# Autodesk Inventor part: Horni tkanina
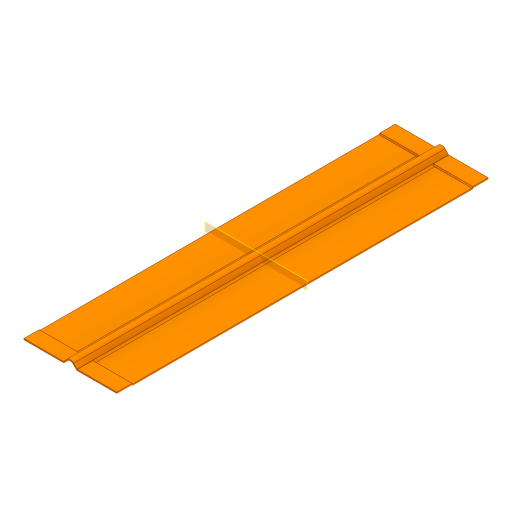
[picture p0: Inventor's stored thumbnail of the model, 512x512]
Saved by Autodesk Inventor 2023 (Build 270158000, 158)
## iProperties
Created: 2025-03
Part Number: Horni tkanina
Material: Všeobecné
Document SubType Name: Modeling
Designer: tomik
Density: 1 g/cm^3
Appearance: Výchozí(1)
Author: tomik
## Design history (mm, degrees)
sketch "Náčrt1"
  geometry: L1 (0, 0)-(0, 10.449); L2 (0, 0)-(6.785, 0); L3 (0, 0)-(0, 4); L4 (0, 0)-(4, 0); L5 (3.268, 0.732)-(0, 4); L6 (0, 0)-(-6.785, 0); L7 (0, 0)-(-4, 0); L8 (-3.268, 0.732)-(0, 4); A1 r 2.5 centre (5.036, 2.5) between (3.268, 0.732) and (5.036, 0); A2 r 2.5 centre (-5.036, 2.5) between (-5.036, 0) and (-3.268, 0.732)
  constraints: 16 end point, 5 point on line, 5 symmetric about line, 4 point on circle, 2 centre point, 2 tangent, 1 horizontal, 1 vertical, 1 other
  dimensions: "d0" = 4 distance of L1.start L3.end; "d3" = 4 distance of L1.start L4.end; "d4" = 5 diameter of A1; "d5" = 5.03553 distance from line of A1.end L1
extrude "Vysunutí1" new body sketch "Náčrt1" distance "d6" = 200; taper "d7" = 0 deg
fillet "Zaoblení1" dims "d8" = 2
feature "Zesílit1" dims "d9" = 0.6, "d10" = 2
sketch "Náčrt2"
  geometry: 1 further point
node "Pracovní rovina1"
sketch "Náčrt3"
  geometry: L1 (0, 0)-(0, 200) reference; L2 (0, 0)-(0.6, 0) reference; L3 (0, 0)-(0, 200) reference; L4 (0, 0)-(0.6, 0) reference; L5 (0.6, 0)-(0.6, 200) reference; L6 (0, 200)-(0.6, 200) reference; 2 further points
extrude "Vysunutí2" join sketch "Náčrt3" stored distance "d12" = 200; taper "d13" = 0 deg
mirror "Zrcadlit1"
sketch "Náčrt4"
  geometry: L1 (0, 0)-(0, 200) reference; L2 (50, 0)-(50, 200) reference; L3 (0, 0)-(50, 0); L4 (50, 0)-(50, 8); L5 (50, 8)-(0, 8); L6 (0, 8)-(0, 0); 3 further points
  constraints: 8 end point, 2 parallel, 1 horizontal, 1 perpendicular, 1 point on line
  dimensions: "d14" = 8 distance between parallel lines of L3 L5
extrude "Vysunutí3" cut sketch "Náčrt4" distance "d15" = 0.5; taper "d16" = 0 deg
fillet "Zaoblení2" dims "d20" = 0.8
node "Pracovní rovina2"
mirror "Zrcadlit2"
chamfer "Zkosení2" distance "d22" = 0.4999; stored, may be unused: second distance "d23" = 2, angle "d24" = 45 deg
chamfer "Zkosení3" distance "d25" = 0.4999; stored, may be unused: second distance "d26" = 2, angle "d27" = 45 deg
sketch "Náčrt5"
  geometry: L1 (0, 200)-(-21.169, 200) reference; L2 (-50, 200)-(-50, 0) reference; L3 (0, 200)-(-50, 200); L4 (-50, 200)-(-50, 191.25); L5 (-50, 191.25)-(0, 191.25); L6 (0, 191.25)-(0, 200); 3 further points
  constraints: 8 end point, 2 parallel, 1 horizontal, 1 perpendicular, 1 point on line
  dimensions: "d28" = 8.75 distance between parallel lines of L3 L5
extrude "Vysunutí4" join sketch "Náčrt5" distance "d29" = 0.5; taper "d30" = 0 deg
sketch "Náčrt6"
  geometry: L1 (-2.9, -0.072)-(-3.268, -0.439) reference; L2 (3.268, -0.439)-(2.9, -0.072) reference; L3 (-2.9, -0.072)-(2.9, -0.072) reference; L4 (-25, -0.672)-(-3.831, -0.672) reference; L5 (-3.831, -0.672)-(3.831, -0.672); A1 r 0.8 centre (-3.831, 0.128) between (-3.831, -0.672) and (-3.444, -0.572) reference; A2 r 0.8 centre (-3.831, 0.128) between (-3.831, -0.672) and (-3.266, -0.437) reference; A3 r 0.8 centre (3.831, 0.128) between (3.444, -0.572) and (3.831, -0.672) reference; A4 r 0.8 centre (3.831, 0.128) between (3.268, -0.439) and (3.831, -0.672) reference; 1 further point
  constraints: 2 end point, 1 collinear
extrude "Vysunutí5" cut sketch "Náčrt6" stored distance "d31" = 0.6; taper "d32" = 0 deg
chamfer "Zkosení4" distance "d33" = 0.5; stored, may be unused: second distance "d34" = 2, angle "d35" = 45 deg
node "Přímé úpravy1"
sketch "Náčrt7"
  geometry: L1 (0, 0)-(21.169, 0) reference; L2 (50, 8.5)-(50, 191.5) reference; L3 (0, 0)-(50, 0); L4 (50, 0)-(50, 8.75); L5 (50, 8.75)-(0, 8.75); L6 (0, 8.75)-(0, 0); 3 further points
  constraints: 8 end point, 2 parallel, 1 horizontal, 1 perpendicular, 1 point on line
  dimensions: "d39" = 8.75 distance between parallel lines of L5 L3
extrude "Vysunutí6" join sketch "Náčrt7" distance "d40" = 0.5; taper "d41" = 0 deg
sketch "Náčrt9"
  geometry: L1 (-2.9, -0.072)-(-3.268, -0.439) reference; L2 (-3.444, -0.572)-(3.444, -0.572) reference; L3 (-2.9, -0.072)-(2.9, -0.072) reference; L4 (3.268, -0.439)-(2.9, -0.072) reference; L5 (3.831, -0.672)-(25, -0.672) reference; L6 (25, -0.072)-(25, -0.672) reference; L7 (3.751, -0.072)-(25, -0.072) reference; L8 (3.692, -0.015)-(1.838, 1.838) reference; L9 (-1.838, 1.838)-(-3.692, -0.015) reference; L10 (-25, -0.072)-(-3.751, -0.072) reference; L11 (-25, -0.072)-(-25, -0.672) reference; L12 (-25, -0.672)-(-3.831, -0.672) reference; L13 (-3.444, -0.572)-(3.444, -0.572) reference; L14 (-2.9, -0.072)-(2.9, -0.072) reference; L15 (-1.414, 1.414)-(-2.9, -0.072) reference; L16 (2.9, -0.072)-(1.414, 1.414) reference; A1 r 0.8 centre (3.831, 0.128) between (3.444, -0.572) and (3.831, -0.672) reference; A2 r 1.9 centre (5.036, 1.328) between (3.692, -0.015) and (3.751, -0.072) reference; A3 r 2.6 centre (0, 0) between (1.838, 1.838) and (-1.838, 1.838) reference; A4 r 1.9 centre (-5.036, 1.328) between (-3.751, -0.072) and (-3.692, -0.015) reference; A5 r 0.8 centre (-3.831, 0.128) between (-3.831, -0.672) and (-3.444, -0.572) reference; A6 r 2 centre (0, 0) between (1.414, 1.414) and (-1.414, 1.414) reference; A7 r 0.8 centre (3.831, 0.128) between (3.268, -0.439) and (3.831, -0.672) reference; A8 r 0.8 centre (-3.831, 0.128) between (-3.831, -0.672) and (-3.268, -0.439) reference; 1 further point
extrude "Vysunutí7" cut sketch "Náčrt9" stored distance "d42" = 10; taper "d43" = 0 deg
chamfer "Zkosení5" distance "d44" = 0.5; stored, may be unused: second distance "d45" = 2, angle "d46" = 45 deg
sketch "Náčrt10"
  geometry: L1 (0.421, 0.1)-(0.387, 0.1) reference; L2 (0.296, 0)-(0, 0) reference; L3 (7.275, 0.1)-(7.242, 0.1) reference; L4 (7.663, 0)-(7.367, 0) reference; A1 r 0.8 centre (0, 0.8) between (0, 0) and (0.387, 0.1) reference; A2 r 2.5 centre (-1.204, 2) between (0.296, 0) and (0.421, 0.1) reference; A3 r 0.8 centre (7.663, 0.8) between (7.275, 0.1) and (7.663, 0) reference; 1 further point
  constraints: 1 other
extrude "Vysunutí8" cut sketch "Náčrt10" stored distance "d47" = 10; taper "d48" = 0 deg
sketch "Náčrt11"
  geometry: 1 further point
chamfer "Zkosení6" distance "d49" = 0.5; stored, may be unused: second distance "d50" = 2, angle "d51" = 45 deg
node "Těleso1"
node "Těleso3"
node "Promítnutá smyčka1"
node "Promítnutá smyčka2"
node "Promítnutá smyčka3"
node "Promítnutá smyčka4"
feature "Posunout1" dims "d38" = 0.25
other parameters: "d11" = 25, "d36" = 0, "d37" = 0
